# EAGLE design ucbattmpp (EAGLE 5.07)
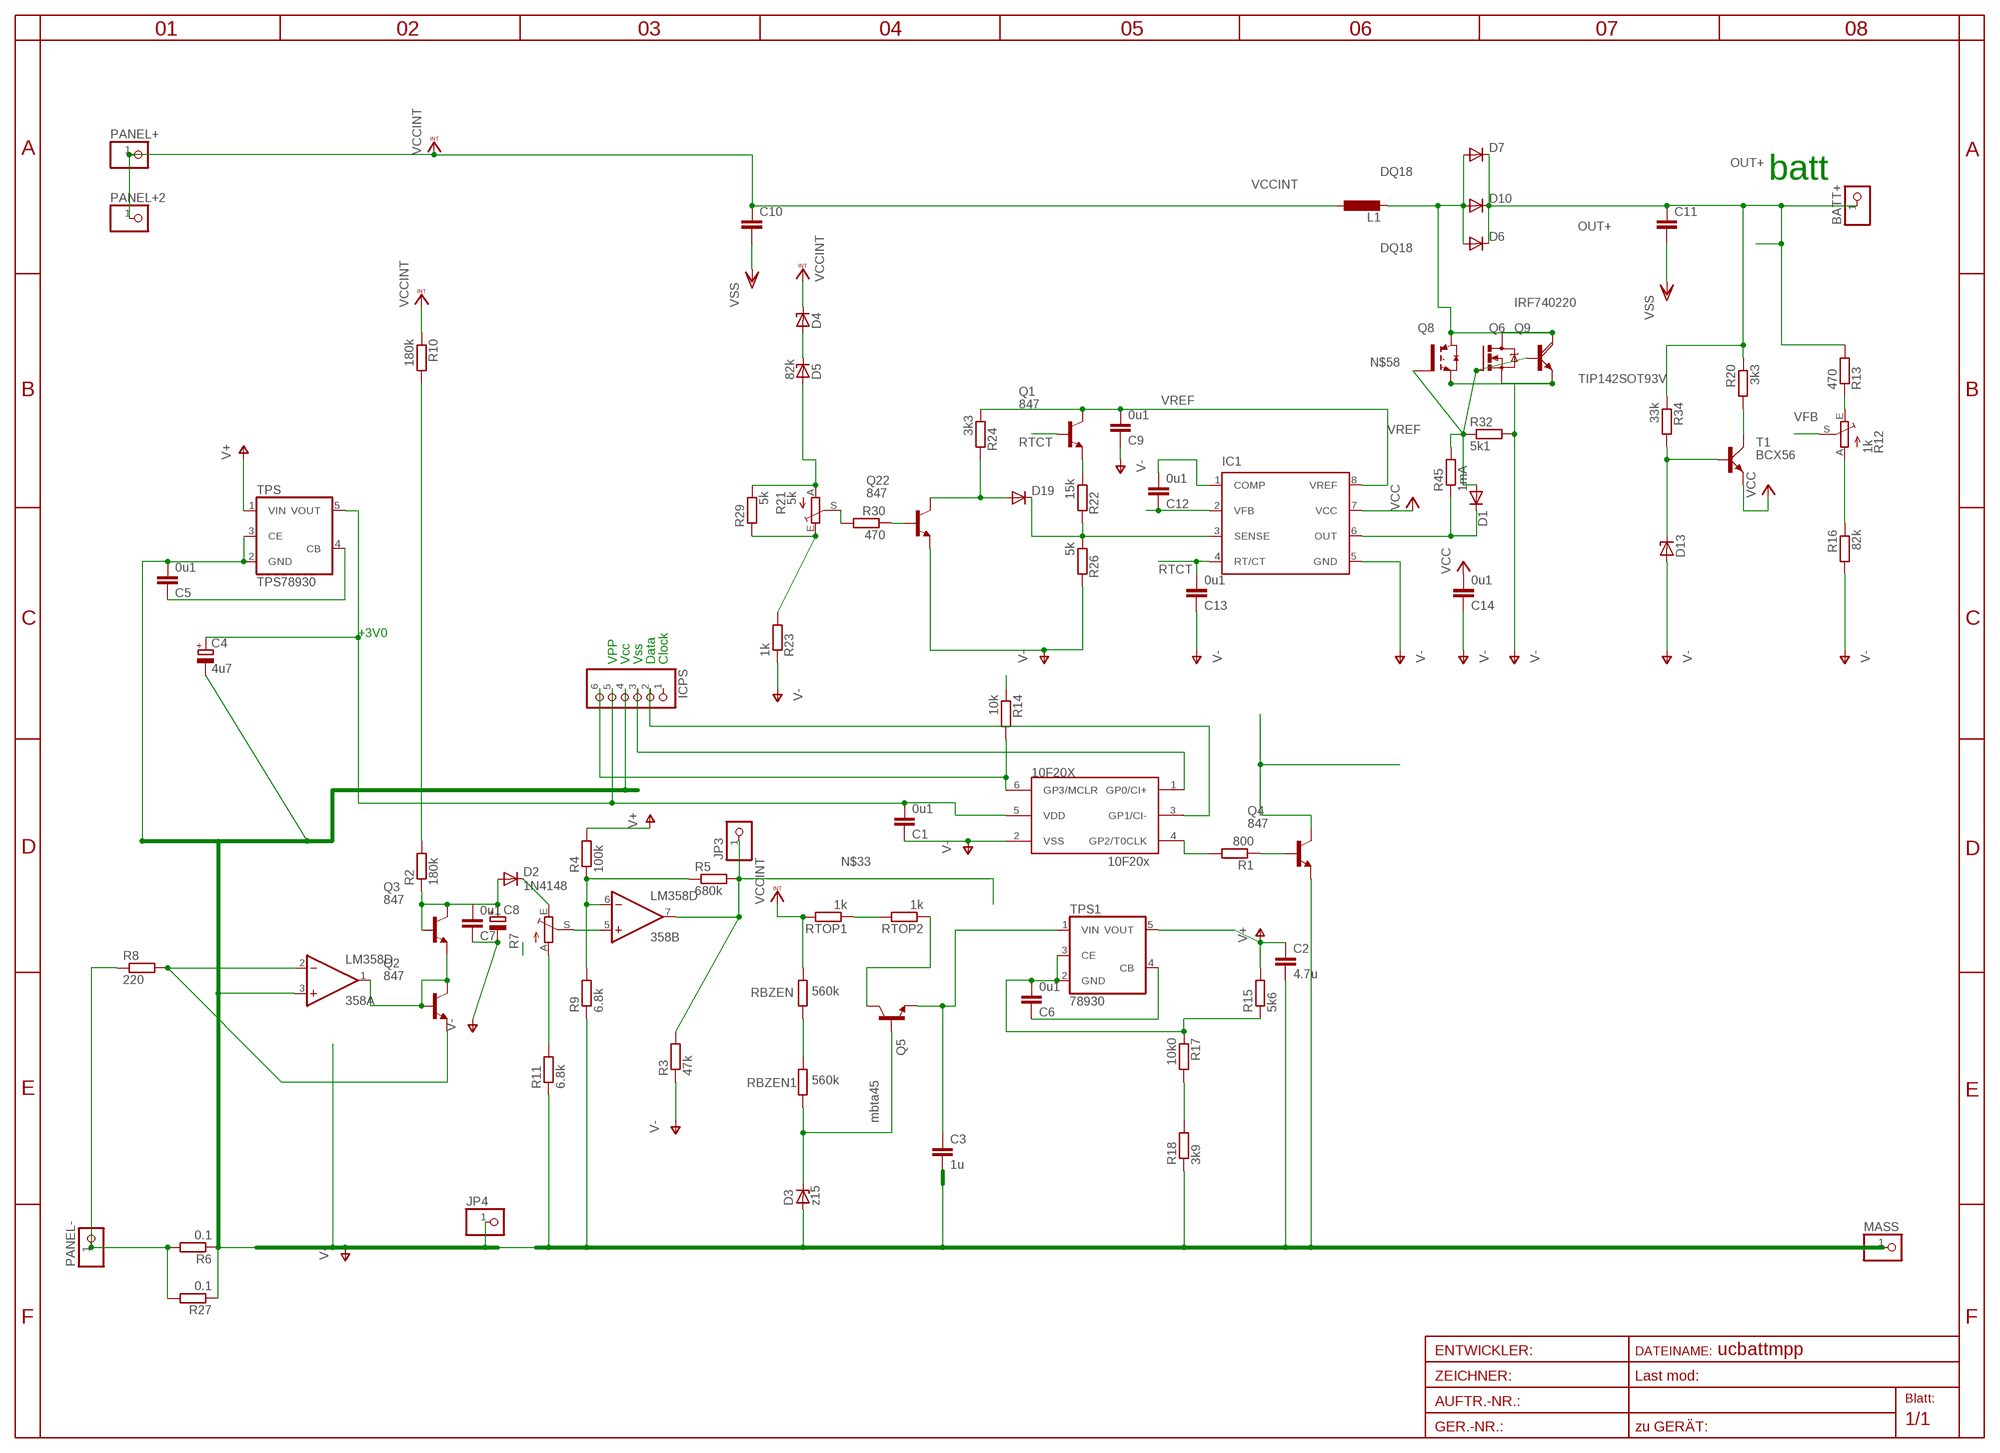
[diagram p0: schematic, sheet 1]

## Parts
10F20X  10F20x  PIC10F204OT  [SOT23-6]
358  LM358D  [SO08]
BATT+  PINHD-1X12MM3  [1X2MM3]
C1  0u1  C-EUC1206  [C1206]
C2  4.7u  C-EUC1206  [C1206]
C3  1u  C-EUC1206  [C1206]
C4  4u7  CPOL-EUSMCA  [SMC_A]
C5  0u1  C-EUC0805  [C0805]
C6  0u1  C-EUC0805  [C0805]
C7  0u1  C-EUC1608  [C1608]
C8  CPOL-EUSMCA  [SMC_A]
C9  0u1  C-EUC1206  [C1206]
C10  C-EU075-052X106  [C075-052X106]
C11  C-EU075-052X106  [C075-052X106]
C12  0u1  C-EUC0805  [C0805]
C13  0u1  C-EUC1206  [C1206]
C14  0u1  C-EUC1206  [C1206]
D1  DIODE-MINIMELF  [MINIMELF]
D2  1N4148  DIODE-SOD80C  [SOD80C]
D3  z15  ZENER-DIODESOD80C  [SOD80C]
D4  ZENER-DIODESOD80C  [SOD80C]
D5  82k  ZENER-DIODESOD80C  [SOD80C]
D6  DIODE-SMC  [SMC]
D7  DIODE-SMC  [SMC]
D10  DIODE-SMC  [SMC]
D13  ZENER-DIODESOD80C  [SOD80C]
D19  DIODE-MINIMELF  [MINIMELF]
IC1  UC1843D8  [SO-08]
ICPS  PINHD-1X6  [1X06BOX]
JP3  PINHD-1X11MM6  [1X1MM8]
JP4  PINHD-1X11MM6  [1X1MM8]
L1  L-EUOPEN6  [OPEN6_3]
MASS  PINHD-1X12MM3  [1X2MM3]
PANEL+  PINHD-1X11MM6  [1X1MM8]
PANEL+2  PINHD-1X12MM3  [1X2MM3]
PANEL-  PINHD-1X12MM3  [1X2MM3]
Q1  847  BC847ASMD  [SOT23]
Q2  847  BC847ALT1SMD  [SOT23]
Q3  847  BC847ALT1SMD  [SOT23]
Q4  847  BC847ALT1SMD  [SOT23]
Q5  mbta45  BC847ALT1SMD  [SOT23]
Q6  IRF740220  [TO220BV]
Q8  IRG4BC15UD-S  [D2PACK]
Q9  TIP142SOT93V  [SOT93V]
Q22  847  BC847ASMD  [SOT23]
R1  800  R-EU_R0805  [R0805]
R2  180k  R-EU_0207/15  [0207/15]
R3  47k  R-EU_R0805  [R0805]
R4  100k  R-EU_R1206  [R1206]
R5  680k  R-EU_R0805  [R0805]
R6  0.1  R-EU_0207/10  [0207/10]
R7  TRIM_EU-S64W  [S64W]
R8  220  R-EU_R0805  [R0805]
R9  6.8k  R-EU_R1206  [R1206]
R10  180k  R-EU_R1206  [R1206]
R11  6.8k  R-EU_R0805  [R0805]
R12  1k  TRIM_EU-S64W  [S64W]
R13  470  R-EU_R0805  [R0805]
R14  10k  R-EU_R0805  [R0805]
R15  5k6  R-EU_R0805  [R0805]
R16  82k  R-EU_R0805  [R0805]
R17  10k0  R-EU_R0805  [R0805]
R18  3k9  R-EU_R0805  [R0805]
R20  3k3  R-EU_R0805  [R0805]
R21  5k  TRIM_EU-S64W  [S64W]
R22  15k  R-EU_R0805  [R0805]
R23  1k  R-EU_R0805  [R0805]
R24  3k3  R-EU_R1206  [R1206]
R26  5k  R-EU_R0805  [R0805]
R27  0.1  R-EU_R3216  [R3216]
R29  5k  R-EU_R0805  [R0805]
R30  470  R-EU_R0805  [R0805]
R32  5k1  R-EU_R0805  [R0805]
R34  33k  R-EU_R0805  [R0805]
R45  1mA  R-EU_R0805  [R0805]
RBZEN  560k  R-EU_R1206  [R1206]
RBZEN1  560k  R-EU_R1206  [R1206]
RTOP1  1k  R-EU_R1206  [R1206]
RTOP2  1k  R-EU_R1206  [R1206]
T1  BCX56  [SOT223]
TPS  TPS78930  TPS78930SOT23-5  [SOT25]
TPS1  78930  TPS78930SOT23-5  [SOT25]

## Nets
CB: D3.C Q5.1(B) RBZEN1.2
DQ18: D6.A D7.A D10.A L1.2 Q6.D Q8.2(C) Q9.C
FB: 358.2(A:-IN) Q2.2(E) R8.2
GND1: C6.1 TPS1.4(CB)
IN-: PANEL-.1 R6.2 R8.1 R27.2
LOB: Q4.3(C)
N$1: Q4.1(B) R1.1
N$2: R7.A R11.2
N$3: Q22.1(B) R30.1
N$4: 10F20X.1(GP0/CI+) ICPS.3
N$5: 10F20X.4(GP2/T0CLK) R1.2
N$6: R2.2 R10.2
N$7: 358.1(A:OUT) Q2.1(B) Q2.3(C) Q3.2(E)
N$8: 10F20X.3(GP1/CI-) ICPS.2
N$9: 10F20X.5(VDD) C1.2 C4.+ ICPS.5 TPS.5(VOUT)
N$10: D19.C IC1.3(SENSE) R22.2 R26.1
N$11: C5.1 TPS.4(CB)
N$12: C7.2 C8.+ D2.A Q3.1(B) Q3.3(C) R2.1
N$13: D2.C R7.E
N$15: 358.5(B:+IN) R7.S
N$16: Q5.3(C) RTOP2.1
N$17: 358.6(B:-IN) R4.1 R5.1 R9.2
N$18: C12.2 IC1.1(COMP)
N$19: RBZEN1.1 RBZEN.2
N$20: R14.1
N$21: R12.A R16.1
N$23: R20.2 T1.2(C)
N$24: Q1.2(E) R22.1
N$25: D1.C IC1.6(OUT) R45.1
N$26: D13.C R34.2 T1.1(B)
N$28: R17.2 R18.2
N$29: RTOP1.1 RTOP2.2
N$30: D4.A D5.C
N$32: D5.A R21.A R29.1
N$33: 358.7(B:OUT) JP3.1 R3.2 R5.2
N$34: R21.E R23.2 R29.2
N$37: R12.E R13.1
N$58: D1.A Q6.G Q8.1(G) Q9.B R32.1 R45.2
N$71: D19.A Q22.3(C) R24.2
OUT+: BATT+.1 C11.1 D6.C D7.C D10.C R13.2 R20.1 R34.1
PIR: 10F20X.6(GP3/MCLR) ICPS.6 R14.2
PRB1: R21.S R30.2
RTCT: C13.2 IC1.4(RT/CT) Q1.1(B)
V15: C3.1 Q5.2(E) TPS1.1(VIN)
V+: C2.1 R4.2 R15.2 TPS1.5(VOUT) TPS.1(VIN)
V-: 10F20X.2(VSS) 358.3(A:+IN) C1.1 C2.2 C3.2 C4.- C5.2 C7.1 C8.- C9.1 C10.2 C11.2 C13.1 C14.1 D3.A D13.A IC1.5(GND) ICPS.4 JP4.1 MASS.1 Q4.2(E) Q6.S Q8.3(E) Q9.E Q22.2(E) R3.1 R6.1 R9.1 R11.1 R16.2 R18.1 R23.1 R26.2 R27.1 R32.2 TPS.2(GND) TPS.3(CE) ; supply symbol labelled VSS
VCC: C14.2 IC1.7(VCC) T1.3(E)
VCCINT: C10.1 D4.C L1.1 PANEL+2.1 PANEL+.1 R10.1 RBZEN.1 RTOP1.2
VFB: C12.1 IC1.2(VFB) R12.S
VREF: C9.2 IC1.8(VREF) Q1.3(C) R24.1
X: C6.2 R15.1 R17.1 TPS1.2(GND) TPS1.3(CE)
Unconnected: ICPS.1

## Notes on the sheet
- batt
- +3V0
- VPP | Vcc | Vss | Data | Clock

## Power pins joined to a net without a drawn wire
V+: 358.8(P:V+)
V-: 358.4(P:V-)

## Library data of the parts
10F20X = microchip-3:PIC10F2*: uPC nW 0,25/0,5k Program Flash memory Comparator
358 = linear:LM358: OP AMP also LM158; LM258; LM2904 Source: http://cache.national.com/ds/LM/LM158.pdf
BATT+ JP3 JP4 MASS PANEL+ PANEL+2 PANEL- = pinhead:PINHD-1X1: PIN HEADER
C1-C3 C5-C7 C9-C14 = rcl:C-EU: CAPACITOR, European symbol
C4 = rcl(2):CPOL-EU: POLARIZED CAPACITOR, European symbol
C8 = rcl:CPOL-EU: POLARIZED CAPACITOR, European symbol
D1 D2 D6 D7 D10 D19 = diode:DIODE-: DIODE
D3-D5 D13 = diode:ZENER-DIODE: Z-Diode
IC1 = texas:UC1843D8: PULSE WIDTH MODULATOR
ICPS = pinhead:PINHD-1X6: PIN HEADER
L1 = rcl:L-EU: INDUCTOR, European symbol
Q1-Q5 Q22 = transistor-npn:BC847*: NPN Transistor
Q6 = transistor-power:IRF740: N-CHANNEL MOS FET
Q8 = transistor-power:IRG4BC15UD-: INSULATED GATE BIPOLAR TRANSISTOR WITH ULTRAFAST SOFT RECOVERY DIODE
Q9 = transistor-power:TIP142: NPN DARLINGTON TRANSISTOR
R1-R6 R8-R11 R13-R18 R20 R22-R24 R26 R27 R29 R30 R34 RBZEN RBZEN1 RTOP1 RTOP2 = rcl:R-EU_: RESISTOR, European symbol
R7 R12 R21 = pot:TRIM_EU-: POTENTIOMETER
R32 R45 = rcl-2:R-EU_: RESISTOR, European symbol
T1 = transistor-power:BCX56
TPS TPS1 = v-reg:TPS78930

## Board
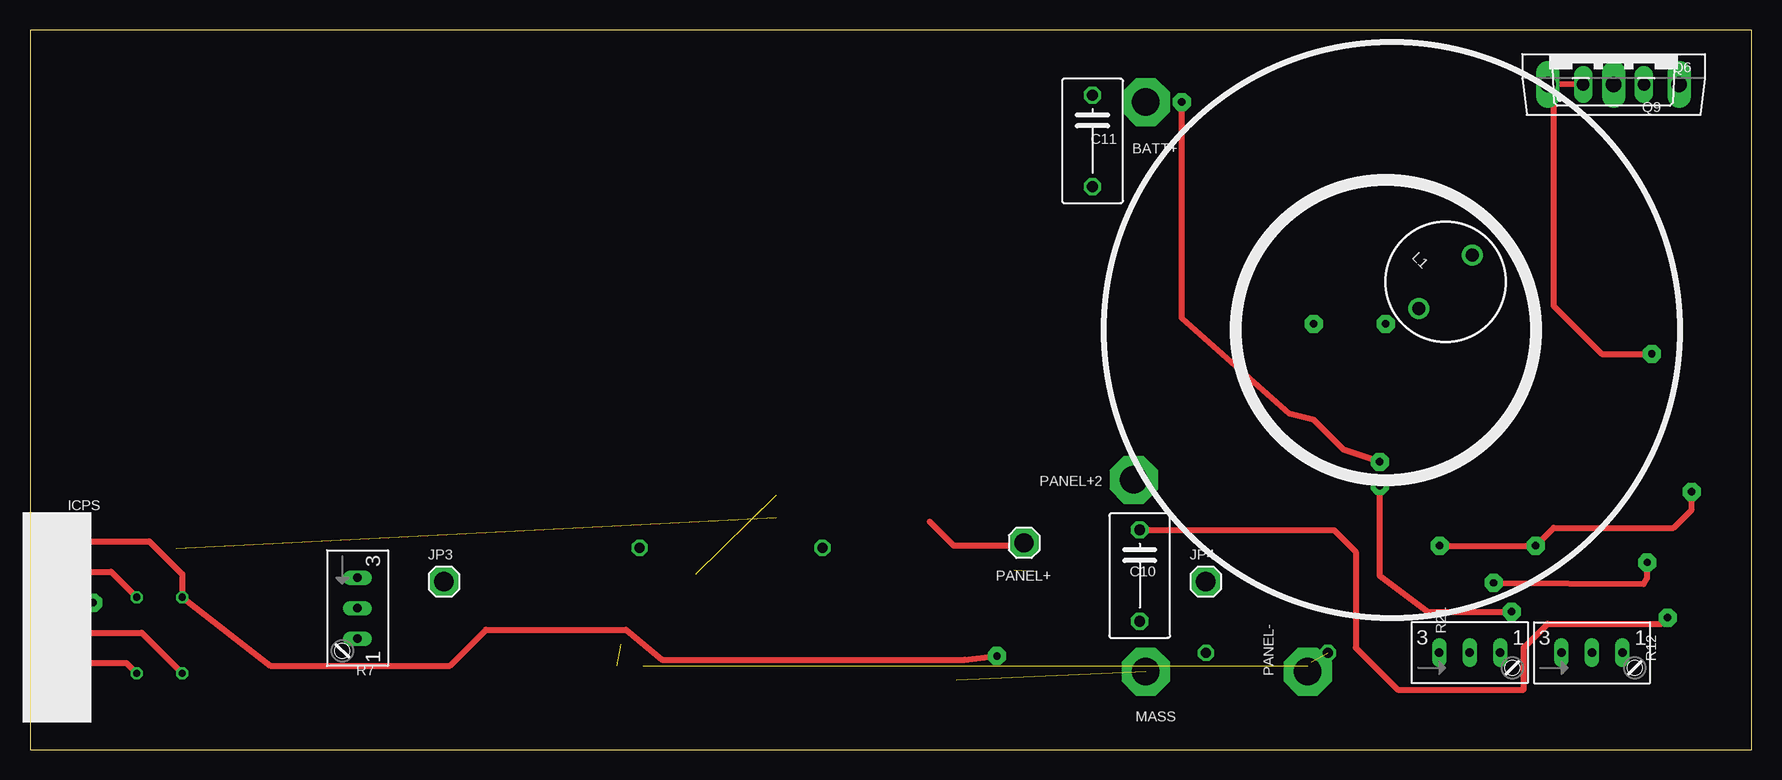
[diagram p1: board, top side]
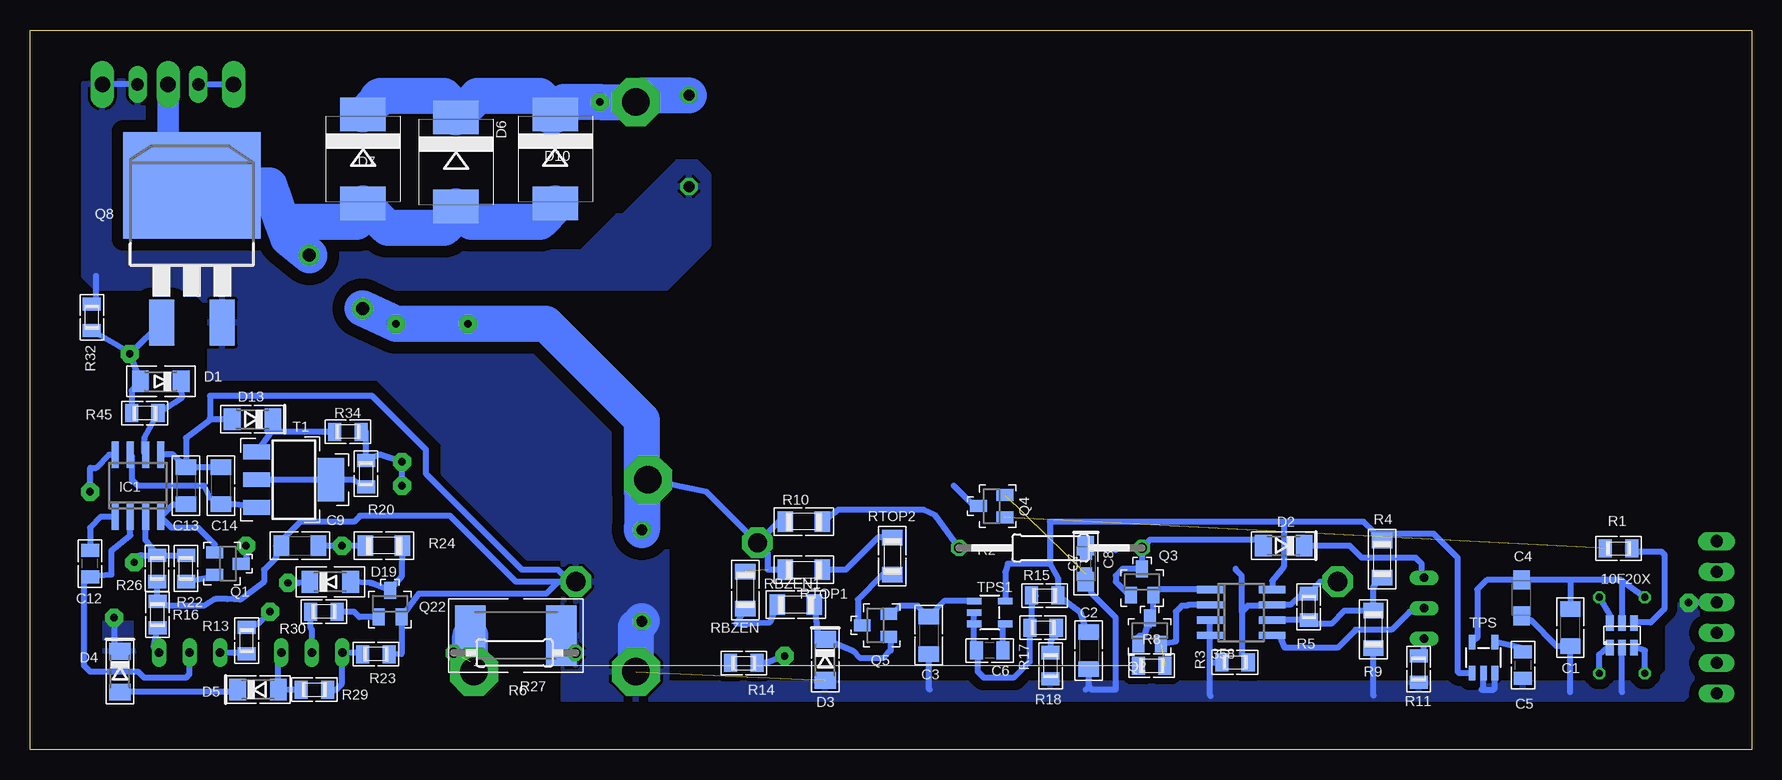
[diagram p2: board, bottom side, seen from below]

Size 143.5 x 60 mm. Coordinates in mm from the lower left corner, seen from the top.
Outline: 0,0 143.5,0 143.5,60 0,60 0,0
Copper layers (1*16): Top 0.035mm / dielectric 1.5mm / Bottom 0.035mm
Design rules "default *": minimum track width 10mil, minimum drill 24mil, track to track 8mil, track to pad 8mil, pad to pad 8mil, via to via 8mil, smd to smd 8mil, copper to edge 4mm, drill to drill 8mil, minimum pad ring 10mil, minimum via ring 8mil, stop-mask expansion 4mil, vias tented up to drill 0mil, thermal gap 10mil

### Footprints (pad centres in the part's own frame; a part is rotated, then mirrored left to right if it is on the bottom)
SOT23-6 = smd 0.635 x 1.27: 1 -1.016,-1.016; 2 0,-1.016; 3 1.016,-1.016; 4 1.016,1.016; 5 0,1.016; 6 -1.016,1.016
SO08 = smd 0.6 x 2.2: 1 -1.905,-2.6; 2 -0.635,-2.6; 3 0.635,-2.6; 4 1.905,-2.6; 5 1.905,2.6; 6 0.635,2.6; 7 -0.635,2.6; 8 -1.905,2.6
1X2MM3 = drill 2.3 pad 4 octagon: 1 0,0
C1206 = smd 1.3 x 1.7: 1 -1.55,0; 2 1.55,0
SMC_A = smd 1.6 x 1.4: + -1.5,0; - 1.5,0
C0805 = smd 1.1 x 1.5: 1 -1.1,0; 2 1.1,0
C1608 = smd 1.1 x 1: 1 -0.85,0; 2 0.85,0
C075-052X106 = drill 0.914 octagon: 1 -3.81,0; 2 3.81,0
MINIMELF = smd 1.4 x 1.8: A 1.7,0; C -1.7,0
SOD80C = smd 1.4 x 1.8: A 1.7,0; C -1.7,0
SMC = smd 2.8 x 3.8: A 3.7,0; C -3.7,0
SO-08 = smd 0.6 x 2.2: 1 -1.905,-2.6; 2 -0.635,-2.6; 3 0.635,-2.6; 4 1.905,-2.6; 5 1.905,2.6; 6 0.635,2.6; 7 -0.635,2.6; 8 -1.905,2.6
1X06BOX = drill 1 long: 1 -6.35,0; 2 -3.81,0; 3 -1.27,0; 4 1.27,0; 5 3.81,0 | drill 1.016 long: 6 6.35,0
1X1MM8 = drill 1.6 pad 2.54 octagon: 1 0,0
OPEN6_3 = drill 1.1 pad 1.778 round: 1 -3.15,0; 2 3.15,0
SOT23 = smd 1 x 1.4: 1 -0.95,-1.1; 2 0.95,-1.1; 3 0,1.1
TO220BV = drill 1.016 long: D 0,-2.54; G -2.54,-2.54; S 2.54,-2.54
D2PACK = smd 2.083 x 3.81: 1 -2.54,-8.89; 3 2.54,-8.89 | smd 11.43 x 8.89: 2 0,2.54
SOT93V = drill 1.3 pad 1.676 long: B -5.461,-2.54; C 0,-2.54; E 5.461,-2.54
R0805 = smd 1.1 x 1.5: 1 -1.1,0; 2 1.1,0
0207/15 = drill 0.813 octagon: 1 -7.62,0; 2 7.62,0
R1206 = smd 1.3 x 1.7: 1 -1.55,0; 2 1.55,0
0207/10 = drill 0.813 octagon: 1 -5.08,0; 2 5.08,0
S64W = drill 0.7 long: A 2.54,1.27; E -2.54,1.27; S 0,1.27
R3216 = smd 2.54 x 5.08: 1 -3.81,0; 2 3.81,0
SOT223 = smd 1.219 x 2.235: 1 -2.311,-3.099; 2 0,-3.099; 3 2.311,-3.099 | smd 3.6 x 2.2: 4 0,3.099
SOT25 = smd 0.55 x 1.2: 1 -0.95,-1.3; 2 0,-1.3; 3 0.95,-1.3; 4 0.95,1.3; 5 -0.95,1.3

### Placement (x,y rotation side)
10F20X  10.79,9.53 0 bottom
358  42.55,11.43 270 bottom
BATT+  93,54 0 top
C1  15.11,10.16 90 bottom
C2  55.24,8.26 270 bottom
C3  68.58,9.53 270 bottom
C4  19.18,12.63 270 bottom
C5  19.05,7.04 270 bottom
C6  63.5,8.26 180 bottom
C7  55.5,15.5 90 bottom
C8  55.5,15.5 270 bottom
C9  121,17 0 bottom
C10  92.5,14.5 270 top
C11  88.56,50.75 270 top
C12  138.5,15.5 90 bottom
C13  130.5,22 270 bottom
C14  127.6,22 270 bottom
D1  132.6,30.7 180 bottom
D2  39,17 180 bottom
D3  77.22,7.48 270 bottom
D4  136,6.5 270 bottom
D5  124.5,5 0 bottom
D6  108,49 270 bottom
D7  115.73,49.25 270 bottom
D10  99.71,49.25 270 bottom
D13  124.96,27.55 180 bottom
D19  118.47,13.98 0 bottom
IC1  134.5,22 0 bottom
ICPS  2.9,11.02 90 top
JP3  34.5,14 0 top
JP4  98,14 0 top
L1  118,39 45 top
MASS  93,6.5 0 top
PANEL+  82.86,17.24 0 top
PANEL+2  92,22.5 0 top
PANEL-  106.5,6.5 90 top
Q1  127,15.5 270 bottom
Q2  50.16,9.89 0 bottom
Q3  50.8,13.97 0 bottom
Q4  63.33,20.3 90 bottom
Q5  73.03,10.35 90 bottom
Q6  132,58 0 top
Q8  130,44.5 0 bottom
Q9  132,58 0 top
Q22  113.49,12.16 0 bottom
R1  11.08,16.77 0 bottom
R2  58.44,16.81 180 bottom
R3  43.05,7.27 0 bottom
R4  30.8,15.88 90 bottom
R5  36.9,11.9 90 bottom
R6  103.11,8.05 180 bottom
R7  26.04,11.79 270 top
R8  50,7 0 bottom
R9  31.52,10.03 90 bottom
R10  79,19 0 bottom
R11  27.75,6.71 90 bottom
R12  130.21,6.8 0 top
R13  125.44,9.08 90 bottom
R14  84,7.21 0 bottom
R15  58.92,12.84 0 bottom
R16  132.88,11.25 90 bottom
R17  59.05,10.16 0 bottom
R18  58.42,6.99 90 bottom
R20  115.5,23 270 bottom
R21  120.01,6.82 0 top
R22  130.5,15.1 90 bottom
R23  114.66,7.96 180 bottom
R24  114,17 0 bottom
R26  132.9,15.1 270 bottom
R27  103,9.5 180 bottom
R29  119.8,5 0 bottom
R30  119,11.5 180 bottom
R32  138.34,36.05 90 bottom
R34  117,26.5 180 bottom
R45  133.93,28.05 180 bottom
RBZEN  83.86,13.29 270 bottom
RBZEN1  79.66,12.07 0 bottom
RTOP1  79,15 180 bottom
RTOP2  71.62,16.12 90 bottom
T1  121.5,22.5 270 bottom
TPS  22.35,7.67 0 bottom
TPS1  63.5,11.43 270 bottom

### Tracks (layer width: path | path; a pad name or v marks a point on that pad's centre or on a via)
CB
  Bottom 0.5: Q5.1 71.75,9.23 71.75,8.26 72.39,7.62 74.3,7.62 74.85,8.18 D3.C 77.72,9.18 RBZEN1.2
DQ18
  Bottom 1.778: 132,47.54 Q9.C
  Bottom 2.54: Q8.2 132,47.54
  Bottom 3: D10.A 99.71,45.29 101,44 106.7,44 D6.A 108,44.5 109,43.5 113.69,43.5 D7.A 116.28,44 122.5,44 | Q8.2 123.54,47.04 122.5,44 | 122.5,44 122,42.65 L1.2
FB  (1 unrouted)
  Bottom 0.5: 358.2 46.94,12.06 47,12 47.5,12 48,11.5 48,9 Q2.2
GND1
  Bottom 0.5: C6.1 62.4,10.28 TPS1.4
IN-  (2 unrouted)
  Bottom 3: PANEL-.1 106.5,7 106.81,7.31 R27.2
LOB
  Bottom 0.5: Q4.3 64.8,20.3 66.5,22
N$1  (1 unrouted)
N$2
  Bottom 0.5: R7.A 27.3,8.26 R11.2
N$3
  Bottom 0.5: Q22.1 116.06,11.06 116.5,11.5 R30.1
N$4  (via drill 0.6)
  Top 0.5: ICPS.3 9.3,9.75 v12.7,6.35
  Bottom 0.5: v12.7,6.35 12.7,7.9 11.99,8.51 10F20X.1
N$5
  Bottom 0.5: 10F20X.4 9.72,10.6 8.4,10.6 7.24,11.76 7.24,16.24 7.5,16.5 9.71,16.5 R1.2
N$6
  Bottom 0.5: R2.2 68.06,19.56 69,20 76.14,20 R10.2
N$7
  Bottom 0.5: 358.1 49.38,13.34 Q3.2 49.9,12.42 49.9,10.9 50.16,10.34 Q2.3 50.66,9.5 51,9.5 51.12,9.38 Q2.1
N$8  (via drill 0.6)
  Top 0.5: ICPS.2 8.03,7.21 v8.89,6.35
  Bottom 0.5: v8.89,6.35 8.89,8.26 10F20X.3
N$9  (via drill 0.6)
  Top 0.5: ICPS.5 6.76,14.83 v8.89,12.7
  Bottom 0.5: 15.24,14.13 10.86,14.13 10.75,14.02 | 15.24,14.13 C4.+ 22.06,14.13 22.86,13.34 22.86,9.3 TPS.5 | v8.89,12.7 10.7,13.97 10.75,14.02 | 10F20X.5 10.79,13.97 10.75,14.02 | C1.2 15.11,14 15.24,14.13
N$10  (via drill 0.6 pad 1.5)
  Top 0.5: v122,13.9 134.5,13.8 134.8,14.3 v134.8,15.6
  Bottom 0.5: IC1.3 133.87,17.46 R26.1 | D19.C 121.12,13.88 v122,13.9 | R26.1 R22.2 | R26.1 134.2,16.2 arc-90 v134.8,15.6
N$11
  Bottom 0.5: TPS.4 19.25,8.47 C5.1
N$12
  Bottom 0.5: D2.A 41,17.5 50.13,17.5 R2.1 | R2.1 52.82,16.78 53.12,16.73 | Q3.1 51.87,12.87 53,14 53,14.5 52.43,15.07 Q3.3 50.82,15.09 R2.1 | 53.12,16.73 53,16.62 | C7.2 C8.+ 55.23,16.73 53.12,16.73
N$13
  Bottom 0.5: D2.C 33.49,16.99 32.5,16 28,16 27.5,15.5 27.5,14.03 R7.E
N$15
  Bottom 0.5: 358.5 39.33,9.53 38.9,8.5 34.5,8.5 33,10 30,10 28.5,11.5 27.59,11.5 R7.S
N$16
  Bottom 0.5: RTOP2.1 72.43,14.57 74.5,12.5 74.5,10.73 Q5.3
N$17
  Bottom 0.5: R4.1 31.52,13.55 R9.2 33.92,11.57 35,10.5 36.59,10.5 R5.1 37.91,10.79 358.6
N$18
  Bottom 0.5: IC1.1 137.6,19.4 138.5,18.5 C12.2
N$19
  Bottom 0.5: RBZEN1.1 81.87,10.57 83.5,10.5 84.61,10.5 RBZEN.2
N$21
  Bottom 0.5: R12.A 133.18,8.51 R16.1
N$23
  Bottom 0.5: T1.2 116.6,22.5 R20.2
N$24
  Bottom 0.5: R22.1 128.25,14.4 Q1.2
N$25
  Bottom 0.5: IC1.6 134,24.73 134,25.5 133.93,26.07 R45.1 130.83,29.37 D1.C
N$26
  Bottom 0.5: R34.2 123.71,26.5 D13.C 123.25,26.65 T1.1
N$28
  Bottom 0.5: R18.2 58.42,9.08 58,9.5 58,10.12 R17.2
N$29
  Bottom 0.5: RTOP1.1 75.52,14.98 72.83,17.67 RTOP2.2
N$30
  Bottom 0.5: D4.A 126.4,4.8 D5.C
N$32
  Bottom 0.5: R29.1 D5.A 122.8,7.84 R21.A
N$33
  Bottom 0.5: R3.2 42.05,7.54 42.5,8 42.5,11.5 | 42.5,11.5 42,12 40.01,12 358.7 38.44,12.06 37.5,13 R5.2 35.95,14 JP3.1 | 42.5,11.5 42.5,14.5 43,15 43,15.1
N$34
  Bottom 0.5: R29.2 118,5 117.5,5.5 117.5,8.06 R21.E 115.89,8.09 R23.2
N$37
  Bottom 0.5: R13.1 125.53,8.07 R12.E
N$58  (via drill 0.6 pad 1.5)
  Top 0.5: Q6.G 126.96,55.54 127,52.5 127,37 131,33 v135.2,33
  Bottom 0.5: 135.09,33.05 R32.1 | 135.09,33.05 Q8.1 | Q6.G Q9.B | R45.2 135.03,29.93 D1.A v135.2,33 135.2,33.45 135.09,33.05
N$71
  Bottom 0.5: R24.2 112.49,14.46 Q22.3 115.11,13.88 D19.A
OUT+  (via drill 0.6 pad 1.5)
  Top 0.5: v96,54 96,36 105,28 107,27.5 109.5,25 v112.5,24 | v123.5,11.5 116.5,11.5 112.5,14.5 v112.5,22
  Bottom 0.5: D7.C 115.55,52.95 | R13.2 125.44,10.06 124.5,10.5 v123.5,11.5 | v112.5,22 v112.5,24 114.4,24.6 R20.1 115.5,26.5 R34.1
  Bottom 3: C11.1 92.44,54.56 BATT+.1 v96,54 99,54 100,53 100,52.74 D10.C 99.71,53.21 101,54.5 106.2,54.5 D6.C 108,53.5 109,54.5 114.19,54.5 | 114.59,54.09 D7.C | 114.19,54.5 114.59,54.09 | 114.19,54.5 arc-90 114.59,54.09
PIR  (via drill 0.6, 0.6 pad 1.5)
  Top 0.5: v80.6,7.8 77.92,7.48 52.67,7.48 49.67,10 38,10 35,7 20.04,7 v12.7,12.7 12.7,14.61 9.94,17.37 ICPS.6
  Bottom 0.5: 10F20X.6 11.81,11.18 v12.7,12.7 | R14.2 82.08,7.21 v80.6,7.8
PRB1
  Bottom 0.5: R30.2 120.1,10.1 120,10 R21.S
RTCT
  Bottom 0.5: Q1.1 128.1,17.1 129.5,18.5 131.69,18.5 IC1.4 131.54,20.45 C13.2
V15
  Bottom 0.5: TPS1.1 67.28,12.38 C3.1 69.5,12 71,12 71.7,11.3 Q5.2
V+
  Bottom 0.5: TPS.1 24.38,6.38 24.5,6.5 24.5,16 26.5,18 31.5,18 31.5,18.18 | 31.5,18.18 R4.2 | 39,19 32.32,19 31.5,18.18 | 39,19 58.5,19 58.5,15.5 | C2.1 55.24,9.74 55.5,10 56,11.5 R15.2 57.82,14.32 58.5,15.5 | TPS1.5 62.2,14.8 62,15.5 58.5,15.5 | 358.8 39.95,14.05 39,15.25 39,19
V-  (via drill 0.6 pad 1.5)  (2 unrouted)
  Top 0.5: ICPS.4 5.21,12.29 v5.25,12.25
  Bottom 0.5: 15.11,4.81 C1.1 16.23,8.62 18.41,10.79 18.84,10.79 C4.- | 10.79,4.81 10F20X.2 | 45.15,7.27 45.15,4.5 45.09,4.45 | 358.3 358.4 45.15,7.27 | v5.25,12.25 4.54,12.25 ICPS.4 | R9.1 31.52,4.53 31.5,4.5 | C3.2 68.58,5.08 68.5,5 | 55.24,5.25 C2.2 | 55.24,5.25 55.5,5 | TPS.3 21.4,5.1 21.5,5 22.5,5 22.35,5.15 TPS.2 | 55.24,5.25 54.99,5 53,5 53,11 55,13 C7.1 C8.- | 45.15,7.27 R3.1 | Q6.S Q9.E | C13.1 130.5,26 128.5,27.5 | 128.5,27.5 128.5,29.5 115,29.5 110.5,25 110.5,23 102.5,15 99.5,15 98.5,14 JP4.1 | 122.75,17.25 121,19 116.5,19 116,19.5 108.5,19.5 103,14 JP4.1 | 122.75,17.25 123,17 123,16 124,15 124,14 126,12.5 127.05,12.55 128.05,12.55 129,12 132,12 R16.2 132.9,12.03 R26.2 | R32.2 138,37.48 138,39.5 | 128.5,27.5 128.54,27.55 D13.A | C13.1 C14.1 | C13.1 131.55,24.6 IC1.5 | R23.1 112.54,7.97 Q22.2 111.1,13 100.5,13 99.5,14 JP4.1 | C9.1 122.55,17.05 122.75,17.25
  Bottom 3: MASS.1 93,10.19 C10.2
  pour Bottom (isolate 0.813): 1.5,12.5 6.5,12 7,11.5 7,6.5 8,5.5 95.5,5.5 96.5,4.5 96.5,3.5 95,2 8,2 5,5 5,9
  pour Bottom (isolate 1): 90.5,17 90.5,4 99,4 99,16 102,16 109,23 109,25.5 114.5,31 128.5,31 128.5,37 130,38.5 138,38.5 139,39.5 139,55.5 138.5,56 135,56 133.5,54.5 133.5,42 134,41.5 97.5,41.5 94.5,44.5 94,44.5 89.5,49 88,49 87,48 87,42 90.5,38.5 115.5,38.5 117.5,36.5 114.5,33.5 99.5,33 94.5,28 94.5,21
VCC
  Bottom 0.5: IC1.7 135,24.46 135,22.5 134.5,22 129,22 128.5,21 C14.2 126.36,20.45 T1.3
VCCINT  (via drill 0.6 pad 1.5)  (1 unrouted)
  Top 0.5: 75,19 77,17 82.62,17 PANEL+.1 | v136.5,11 136,10.5 126.5,10.5 124.5,8.5 124.5,5 114,5 110.5,8.5 110.5,16.5 108.69,18.31 C10.1
  Bottom 0.5: PANEL+.1 83.86,17.34 | PANEL+.1 82,16.38 82,15 RTOP1.2 | PANEL+.1 81.1,19 R10.1 | PANEL+2.1 87.12,21.5 PANEL+.1 | D4.C 136.5,8.7 v136.5,11
  Bottom 3: L1.1 v113,35.5 v107,35.5 100.5,35.5 92.5,27.5 92.5,21.5 | PANEL+2.1 92.5,21.5 | 92.5,18.5 C10.1 92.5,21.5
  pour Bottom (isolate 1.27, rank 2): 133.5,10.5 137.5,10.5 140,8 140,7.5 139.5,7 134,7 133.5,7.5
VFB
  Bottom 0.5: IC1.2 135.13,17.86 136.7,16.6 136.7,14.6 138.4,14.5 C12.1 139,13.9 139,7 138.5,6.5 134.5,6.5 134,6 130.5,6 130.21,6.29 R12.S
VREF  (via drill 0.6 pad 1.5)
  Top 0.5: v117.5,17 v125.5,17 127,18.5 137,18.5 138.5,20 v138.5,21.5
  Bottom 0.5: IC1.8 136.9,24.6 138,23.5 138.45,23.5 138.5,23.45 v138.5,21.5 | R24.1 v117.5,17 C9.2 | v125.5,17 125.5,15.9 Q1.3
X
  Bottom 0.5: R15.1 59.66,12.84 60,12 60,11.01 R17.1 60.16,7.34 61.5,6 64,6 64.5,6.5 64.5,8.15 C6.2 64.8,8.46 TPS1.3 TPS1.2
